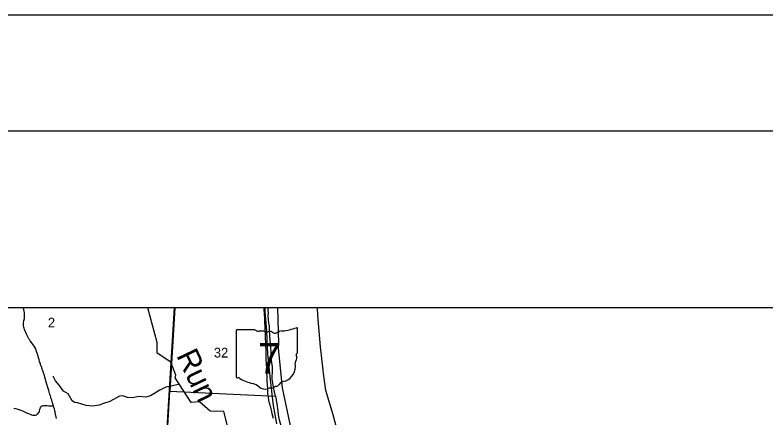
# Model space of a CAD drawing. Extents: x 396.2 to 468.4, y 232.6 to 279.1.
# Drawn here: x 421.28 to 424.52, y 277.383 to 279.121 of the extents above; entities that cross this region are included whole.
import ezdxf

# ---------------------------------------------------------------- set-up
doc = ezdxf.new("R2010")
doc.units = 0
for name, color, linetype in [('Default', 7, 'Continuous'), ('GM_X_County_Road', 7, 'Continuous'), ('GM_X_Major_River', 7, 'Continuous'), ('GM_X_Minor_River', 7, 'Continuous'), ('GM_X_Minor_River_Text', 7, 'Continuous'), ('GM_X_Section', 7, 'Continuous'), ('GM_X_Section_Text', 7, 'Continuous'), ('GM_X_State_Location', 7, 'Continuous'), ('GM_X_State_Route', 7, 'Continuous'), ('GM_X_State_Shield', 7, 'Continuous'), ('GM_X_Township_Road', 7, 'Continuous'), ('SH_Border', 7, 'Continuous'), ('SH_Cut_Line', 7, 'Continuous'), ('TX_P_1', 7, 'Continuous')]:
    doc.layers.add(name, color=color, linetype=linetype)

msp = doc.modelspace()

# ---------------------------------------------------------------- linework, layer by layer
at = {"layer": 'Default'}
msp.add_lwpolyline([(420.82, 276.3196), (421.3281, 276.2897), (421.3374, 276.2902), (421.3462, 276.2904), (421.3559, 276.2899), (421.3682, 276.2886), (421.3714, 276.2883), (421.3763, 276.2876), (421.3831, 276.287), (421.3924, 276.2866), (421.4063, 276.2861), (421.4152, 276.2862), (421.4272, 276.2863), (421.4332, 276.2865), (421.4379, 276.2877), (421.4411, 276.2892), (421.4419, 276.2897), (421.5448, 276.2853), (421.871, 276.2694), (421.9162, 277.0067), (421.9279, 277.1991), (421.9682, 277.8582), (415.7353, 277.8582)], dxfattribs=at)
for points in [[(421.97, 277.8582), (420.9126, 277.8582), (420.8756, 277.3198), (421.9349, 277.2729), (421.9483, 277.4985)], [(422.4135, 277.8582), (421.9682, 277.8582), (421.9279, 277.1991), (421.9162, 277.0067), (422.3899, 276.9811), (422.5697, 276.9693), (422.7085, 276.9638), (422.6622, 277.0091), (422.6087, 277.078), (422.5247, 277.2095), (422.4767, 277.3093), (422.434, 277.5135), (422.4174, 277.6839), (422.4178, 277.704)], [(422.3721, 277.8582), (421.97, 277.8582), (421.9483, 277.4985), (422.4032, 277.4779), (422.399, 277.4966), (422.3956, 277.5155), (422.3921, 277.5337), (422.3901, 277.55), (422.3893, 277.5651), (422.3908, 277.5795), (422.3907, 277.6049), (422.3887, 277.6216), (422.3856, 277.6447), (422.3859, 277.6685), (422.3836, 277.6852), (422.3808, 277.7189), (422.38, 277.7352), (422.3784, 277.7674), (422.3783, 277.781), (422.3757, 277.7917), (422.3733, 277.8076), (422.3718, 277.8231), (422.3744, 277.8364), (422.3728, 277.8462)]]:
    msp.add_lwpolyline(points, close=True, dxfattribs=at)
at = {"layer": 'GM_X_County_Road'}
msp.add_lwpolyline([(421.4595, 277.3805), (421.4551, 277.3992), (421.4531, 277.4076), (421.4526, 277.41), (421.4516, 277.4142), (421.4496, 277.422), (421.4487, 277.4255), (421.4477, 277.4291), (421.4465, 277.4332), (421.4461, 277.4345), (421.4433, 277.4439), (421.4417, 277.4492), (421.4402, 277.454), (421.4383, 277.4599), (421.4365, 277.4658), (421.4343, 277.473), (421.4326, 277.4783), (421.4308, 277.4842), (421.4289, 277.4901), (421.427, 277.4961), (421.4254, 277.5014), (421.4238, 277.5067), (421.4226, 277.5108), (421.4215, 277.515), (421.4204, 277.519), (421.4199, 277.5206), (421.4193, 277.5228), (421.4188, 277.5244), (421.4162, 277.5333), (421.4089, 277.5594), (421.4068, 277.5657), (421.4051, 277.5711), (421.4035, 277.5758), (421.4023, 277.5793), (421.3988, 277.5892), (421.397, 277.5945), (421.3962, 277.5968), (421.3949, 277.6002), (421.3935, 277.6043), (421.392, 277.6097), (421.3882, 277.62), (421.3861, 277.6265), (421.3834, 277.6347), (421.381, 277.6432), (421.3791, 277.6498), (421.3765, 277.6586), (421.3744, 277.6659), (421.3717, 277.6747), (421.3692, 277.6807), (421.3669, 277.6856), (421.3627, 277.693), (421.3588, 277.6988), (421.3551, 277.7034), (421.3508, 277.709), (421.3457, 277.7157), (421.3417, 277.7215), (421.3396, 277.725), (421.3365, 277.7299), (421.3327, 277.7382), (421.3295, 277.7452), (421.3269, 277.7516), (421.3237, 277.7582), (421.3209, 277.7653), (421.3194, 277.7701), (421.318, 277.7754), (421.3167, 277.7801), (421.3163, 277.7855), (421.3167, 277.7933), (421.3175, 277.7988), (421.3183, 277.8036), (421.3192, 277.8078), (421.3201, 277.8124), (421.3209, 277.8173), (421.3214, 277.8231), (421.3214, 277.8308), (421.321, 277.8364), (421.3199, 277.844), (421.3181, 277.851), (421.3169, 277.8552), (421.3161, 277.8582)], dxfattribs=at)
at = {"layer": 'GM_X_Major_River'}
for points in [[(422.3577, 277.8582), (422.3573, 277.8444), (422.3648, 277.7564), (422.3694, 277.6581), (422.3815, 277.548), (422.3933, 277.4376), (422.4084, 277.3583)], [(422.6678, 277.3415), (422.6521, 277.3969), (422.6218, 277.5012), (422.6117, 277.5755), (422.6101, 277.5888), (422.5976, 277.6894), (422.5872, 277.8256), (422.585, 277.8582)]]:
    msp.add_lwpolyline(points, dxfattribs=at)
at = {"layer": 'GM_X_Minor_River'}
for points in [[(422.4105, 277.3353), (422.3947, 277.3413), (422.3826, 277.307), (422.3367, 277.3298), (422.316, 277.3201), (422.3383, 277.2956), (422.291, 277.2838), (422.2796, 277.3437), (422.2306, 277.3486), (422.1972, 277.349), (422.1811, 277.4115), (422.1219, 277.4129), (422.0985, 277.4324), (422.0766, 277.4523), (422.0406, 277.4501), (421.9716, 277.5565), (421.9741, 277.568), (421.9521, 277.6232), (421.8935, 277.6629), (421.8933, 277.7092), (421.8533, 277.8582)], [(421.9893, 277.5292), (421.9542, 277.5199), (421.9314, 277.5157), (421.9045, 277.5031), (421.8651, 277.4791), (421.8446, 277.4737), (421.8139, 277.476), (421.7866, 277.4699), (421.7654, 277.4714), (421.7457, 277.479), (421.7313, 277.4778), (421.6896, 277.4546), (421.6615, 277.4462), (421.6433, 277.4378), (421.6152, 277.4336), (421.5872, 277.4377), (421.5501, 277.4487), (421.5387, 277.4506), (421.5266, 277.4567), (421.5095, 277.4875), (421.4894, 277.4992), (421.4701, 277.5243), (421.4546, 277.5441), (421.4451, 277.5642)]]:
    msp.add_lwpolyline(points, dxfattribs=at)
at = {"layer": 'GM_X_Section'}
msp.add_lwpolyline([(422.4032, 277.4779), (422.4052, 277.4689), (422.4083, 277.4527), (422.411, 277.4341), (422.4129, 277.422), (422.4133, 277.4129), (422.4157, 277.3966), (422.4203, 277.375), (422.4249, 277.3561), (422.4265, 277.3459), (422.4307, 277.3323), (422.4349, 277.3198), (422.4421, 277.3024), (422.4464, 277.2865), (422.4521, 277.2687), (422.4567, 277.2554), (422.4593, 277.2453), (421.9349, 277.2729), (421.9483, 277.4985)], close=True, dxfattribs=at)
at = {"layer": 'GM_X_State_Route'}
msp.add_lwpolyline([(422.3952, 277.3813), (422.3926, 277.3909), (422.3898, 277.4016), (422.3874, 277.4112), (422.3846, 277.422), (422.3821, 277.4322), (422.3806, 277.4388), (422.3787, 277.4467), (422.3757, 277.4607), (422.3738, 277.4717), (422.3724, 277.4803), (422.3714, 277.4896), (422.3702, 277.5089), (422.3683, 277.5449), (422.3677, 277.5591), (422.3669, 277.5808), (422.3662, 277.5982), (422.3651, 277.6174), (422.3641, 277.6379), (422.3635, 277.6565), (422.3631, 277.6683), (422.362, 277.7006), (422.3616, 277.7111), (422.3611, 277.7229), (422.3606, 277.7341), (422.3601, 277.7446), (422.3595, 277.7583), (422.3592, 277.7664), (422.3588, 277.7769), (422.3579, 277.7973), (422.3573, 277.811), (422.3557, 277.8526), (422.3555, 277.8582)], dxfattribs=at)
at = {"layer": 'GM_X_State_Shield'}
for p, q in [((422.2347, 277.7605), (422.2347, 277.5604)), ((422.3145, 277.764), (422.2373, 277.764)), ((422.4983, 277.6642), (422.4983, 277.7689)), ((422.4983, 277.6643), (422.4983, 277.6642))]:
    msp.add_line(p, q, dxfattribs=at)
for centre, radius, start, end in [((422.2377, 277.7609), 0.00305, 98.1301, 188.1301), ((422.3329, 277.7872), 0.0296, 231.6195, 271.1119), ((422.3427, 277.6516), 0.1064, 80.4867, 94.9883), ((422.3668, 277.762), 0.00855, 219.7921, 297.1024), ((422.3794, 277.7389), 0.0178, 54.4667, 119.1411), ((422.4023, 277.7706), 0.0214, 233.8562, 294.8282), ((422.4401, 277.7028), 0.0563, 97.3462, 120.7689), ((422.4044, 278.0368), 0.2796, 275.8445, 288.9065), ((422.4954, 277.7694), 0.00294, 351.8621, 97.738), ((422.4977, 277.6565), 0.00454, 107.944, 210.337), ((422.4688, 277.6433), 0.0273, 340.033, 23.6496), ((422.4952, 277.6638), 0.00314, 289.6038, 7.7341), ((422.4201, 277.6071), 0.0699, 292.3089, 8.9858), ((422.5089, 277.6204), 0.0198, 136.8065, 186.9296), ((422.2377, 277.56), 0.00308, 171.9584, 258.3066), ((422.2382, 277.5804), 0.0235, 267.339, 280.6039), ((422.243, 277.5489), 0.00848, 29.7484, 93.2717), ((422.3501, 277.7287), 0.2019, 240.4129, 257.1985), ((422.2899, 277.4705), 0.0632, 47.1842, 75.836), ((422.3843, 277.5329), 0.0214, 268.777, 315.5493), ((422.4036, 277.5135), 0.00601, 65.7517, 132.6484), ((422.401, 277.541), 0.0226, 282.8732, 323.2771), ((422.4496, 277.5042), 0.0383, 94.4031, 142.5768), ((422.3582, 277.5479), 0.0401, 230.7004, 286.2918), ((422.3814, 277.4787), 0.0329, 85.6951, 111.2099)]:
    msp.add_arc(centre, radius, start, end, dxfattribs=at)
at = {"layer": 'GM_X_Township_Road'}
msp.add_lwpolyline([(421.2742, 277.4253), (421.2815, 277.4244), (421.2876, 277.4231), (421.2958, 277.4204), (421.3051, 277.4169), (421.3129, 277.4134), (421.3204, 277.4101), (421.3298, 277.406), (421.338, 277.4024), (421.3514, 277.3971), (421.3568, 277.3956), (421.3606, 277.3951), (421.365, 277.3952), (421.3687, 277.3959), (421.3723, 277.3972), (421.3756, 277.3991), (421.3785, 277.4016), (421.3814, 277.405), (421.3837, 277.4088), (421.3854, 277.4129), (421.3875, 277.4213), (421.3892, 277.4273), (421.3904, 277.43), (421.3918, 277.4319), (421.3935, 277.4335), (421.396, 277.4351), (421.3995, 277.4361), (421.4037, 277.4366), (421.4124, 277.4367), (421.4193, 277.4365), (421.4253, 277.4362), (421.4376, 277.4352), (421.4461, 277.4345)], dxfattribs=at)
at = {"layer": 'SH_Border'}
msp.add_lwpolyline([(397.7027, 278.6206), (429.7027, 278.6206), (429.7027, 257.6206), (397.7027, 257.6206)], close=True, dxfattribs=at)
at = {"layer": 'SH_Cut_Line'}
msp.add_lwpolyline([(396.2027, 257.1206), (430.2027, 257.1206), (430.2027, 279.1206), (396.2027, 279.1206)], close=True, dxfattribs=at)
msp.add_lwpolyline([(422.4767, 277.3093), (422.434, 277.5135), (422.4174, 277.6839), (422.4178, 277.704), (422.4135, 277.8582), (413.8513, 277.8582)], dxfattribs=at)
at = {"layer": 'TX_P_1'}
msp.add_line((427.4513, 277.8582), (413.8513, 277.8582), dxfattribs=at)

# ---------------------------------------------------------------- texts
at = {"layer": 'GM_X_Minor_River_Text'}
msp.add_text('Run', height=0.0947, rotation=295.5123, dxfattribs=at).set_placement((421.9743, 277.6527))
at = {"layer": 'GM_X_Section_Text'}
for s, height, p in [('2', 0.0419, (421.4217, 277.7735)), ('32', 0.04186, (422.1379, 277.644))]:
    msp.add_text(s, height=height, rotation=0, dxfattribs=at).set_placement(p)
at = {"layer": 'GM_X_State_Location'}
for s in ['s', 'r']:
    msp.add_text(s, height=0.000189, dxfattribs=at).set_placement((422.3635, 277.6472))
msp.add_text('7', height=0.000189, rotation=0, dxfattribs=at).set_placement((422.335, 277.6334))
at = {"layer": 'GM_X_State_Shield'}
msp.add_text('7', height=0.1318, dxfattribs=at).set_placement((422.3287, 277.5745))

doc.saveas('drawing.dxf')
